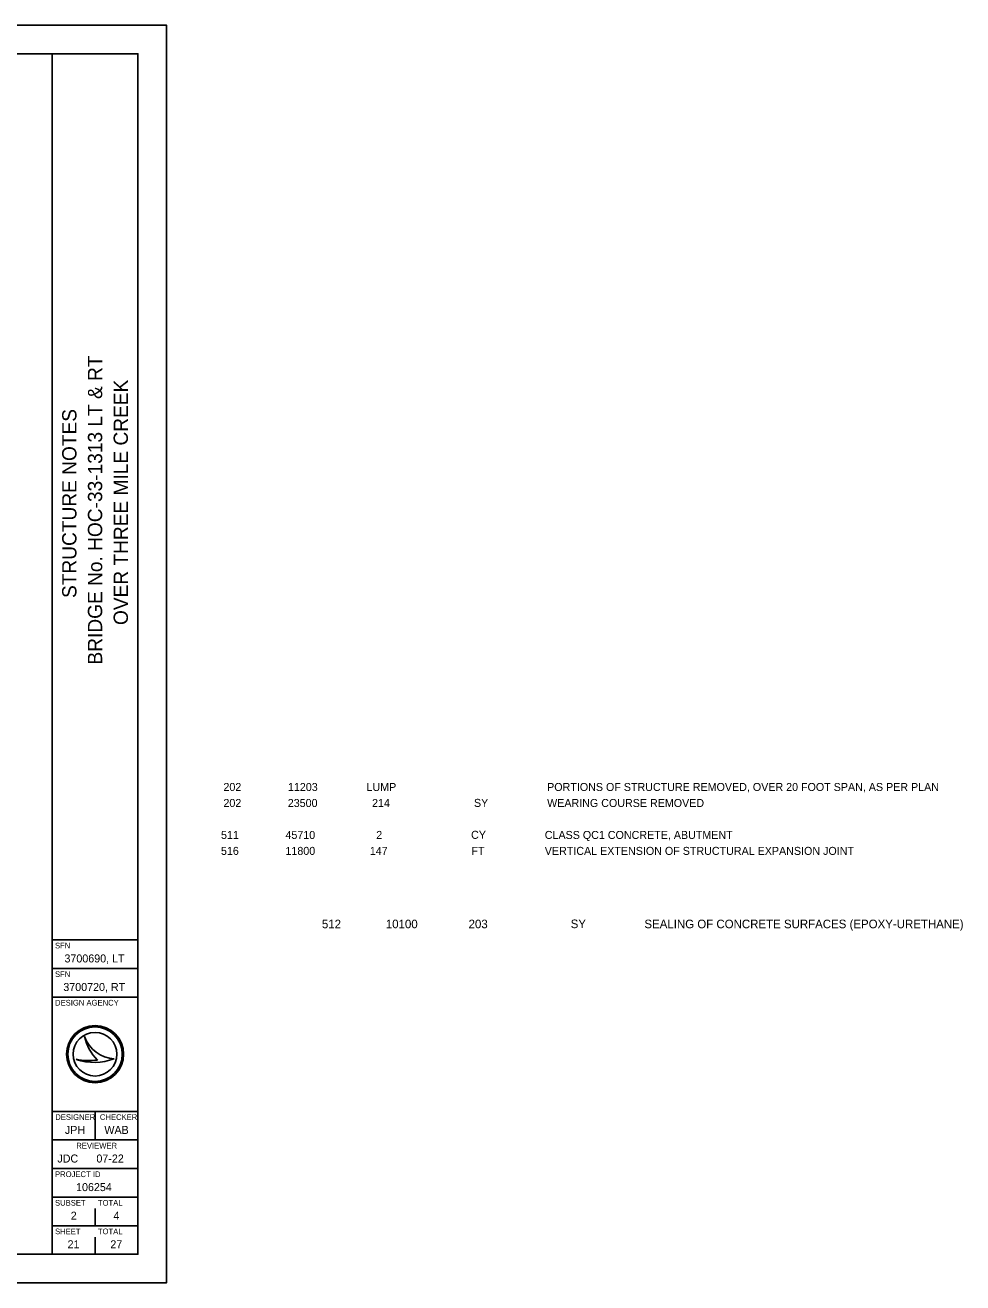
# Model space of a CAD drawing. Extents: x 55 to 102.9, y -8.3 to 13.7.
# Drawn here: x 86.49 to 102.89, y -8.33 to 13.67 of the extents above; entities that cross this region are included whole.
import ezdxf

# ---------------------------------------------------------------- set-up
doc = ezdxf.new("R2010")
doc.units = 0
for name, color, linetype in [('BR_P_Gen_Text', 7, 'Continuous'), ('SH_Border', 7, 'Continuous'), ('SH_Cut_Line', 7, 'Continuous'), ('SH_Data', 7, 'Continuous'), ('TX_P_1', 7, 'Continuous')]:
    doc.layers.add(name, color=color, linetype=linetype)

msp = doc.modelspace()

# ---------------------------------------------------------------- linework, layer by layer
at = {"layer": 'SH_Border'}
for p, q in [((86.958, -7.833), (86.958, 13.167)), ((86.958, -2.333), (88.458, -2.333)), ((86.958, -2.833), (88.458, -2.833)), ((86.958, -3.333), (88.458, -3.333)), ((86.958, -5.333), (88.458, -5.333)), ((87.708, -5.333), (87.708, -5.833)), ((86.958, -5.833), (88.458, -5.833)), ((86.958, -6.333), (88.458, -6.333)), ((86.958, -6.833), (88.458, -6.833)), ((86.958, -7.333), (88.458, -7.333))]:
    msp.add_line(p, q, dxfattribs=at)
msp.add_lwpolyline([(56.458, 13.167), (88.458, 13.167), (88.458, -7.833), (56.458, -7.833)], close=True, dxfattribs=at)
at = {"layer": 'SH_Cut_Line'}
msp.add_lwpolyline([(54.958, -8.333), (88.958, -8.333), (88.958, 13.667), (54.958, 13.667)], close=True, dxfattribs=at)
at = {"layer": 'SH_Data'}
for p, q in [((87.708, -2.658), (87.708, -2.658)), ((87.708, -3.158), (87.708, -3.158)), ((87.525, -4.023), (87.525, -4.023)), ((87.708, -4.333), (87.708, -4.333)), ((87.375, -4.423), (87.375, -4.423)), ((88.045, -4.414), (88.045, -4.414)), ((87.708, -7.333), (87.708, -7.033)), ((87.333, -7.658), (87.333, -7.658)), ((87.708, -7.833), (87.708, -7.533))]:
    msp.add_line(p, q, dxfattribs=at)
for radius in [0.5, 0.477, 0.477, 0.382]:
    msp.add_circle((87.708, -4.333), radius, dxfattribs=at)
for centre, radius, start, end in [((88.074, -3.835), 0.58, 198.9257, 198.9319), ((88.304, -3.863), 0.796, 191.6379, 191.6421), ((88.074, -3.835), 0.58, 198.9319, 267.1657), ((88.304, -3.863), 0.796, 191.6421, 226.0947), ((87.697, -3.463), 1.013, 251.4576, 290.0832), ((87.606, -3.178), 1.266, 259.4964, 259.4995), ((87.697, -3.463), 1.013, 251.4527, 251.4576), ((87.606, -3.178), 1.266, 259.4995, 276.6672)]:
    msp.add_arc(centre, radius, start, end, dxfattribs=at)

# ---------------------------------------------------------------- texts
at = {"layer": 'BR_P_Gen_Text'}
for s, height, p in [('202', 0.14, (89.954, 0.271)), ('11203', 0.14, (91.083, 0.271)), ('LUMP', 0.14, (92.457, 0.271)), ('202', 0.14, (89.954, -0.009)), ('23500', 0.14, (91.08, -0.009)), ('214', 0.14, (92.554, -0.009)), ('SY', 0.14, (94.337, -0.007)), ('511', 0.14, (89.912, -0.568)), ('45710', 0.14, (91.039, -0.568)), ('2', 0.14, (92.627, -0.568)), ('CY', 0.14, (94.287, -0.566)), ('516', 0.14, (89.911, -0.847)), ('11800', 0.14, (91.039, -0.847)), ('147', 0.14, (92.515, -0.847)), ('FT', 0.14, (94.294, -0.846)), ('512', 0.15, (91.677, -2.13)), ('10100', 0.15, (92.795, -2.13)), ('203', 0.15, (94.243, -2.13)), ('SY', 0.15, (96.029, -2.128))]:
    msp.add_text(s, height=height, dxfattribs=at).set_placement(p)
at = {"layer": 'SH_Data'}
for s, p in [('BRIDGE No. HOC-33-1313 LT & RT', (87.833, 2.483)), ('OVER THREE MILE CREEK', (88.283, 3.174)), ('STRUCTURE NOTES', (87.383, 3.647))]:
    msp.add_text(s, height=0.25, rotation=90, dxfattribs=at).set_placement(p)
for s, height, p in [('SFN', 0.1, (87.008, -2.483)), ('3700690, LT', 0.14, (87.173, -2.728)), ('SFN', 0.1, (87.008, -2.983)), ('3700720, RT', 0.14, (87.153, -3.228)), ('DESIGN AGENCY', 0.1, (87.008, -3.483)), ('DESIGNER', 0.1, (87.012, -5.483)), ('CHECKER', 0.1, (87.793, -5.483)), ('JPH', 0.14, (87.181, -5.728)), ('WAB', 0.14, (87.871, -5.728)), ('REVIEWER', 0.1, (87.38, -5.983)), ('JDC', 0.14, (87.049, -6.228)), ('07-22', 0.14, (87.732, -6.228)), ('PROJECT ID', 0.1, (87.008, -6.483)), ('106254', 0.14, (87.376, -6.728)), ('SUBSET', 0.1, (87.008, -6.983)), ('TOTAL', 0.1, (87.758, -6.983)), ('2', 0.14, (87.283, -7.228)), ('4', 0.14, (88.03, -7.228)), ('SHEET', 0.1, (87.008, -7.483)), ('TOTAL', 0.1, (87.758, -7.483)), ('21', 0.14, (87.227, -7.728)), ('27', 0.14, (87.976, -7.728))]:
    msp.add_text(s, height=height, dxfattribs=at).set_placement(p)
at = {"layer": 'TX_P_1'}
for s, height, p in [('PORTIONS OF STRUCTURE REMOVED, OVER 20 FOOT SPAN, AS PER PLAN', 0.14, (95.617, 0.271)), ('WEARING COURSE REMOVED', 0.14, (95.617, -0.009)), ('CLASS QC1 CONCRETE, ABUTMENT', 0.14, (95.576, -0.568)), ('VERTICAL EXTENSION OF STRUCTURAL EXPANSION JOINT', 0.14, (95.576, -0.847)), ('SEALING OF CONCRETE SURFACES (EPOXY-URETHANE)', 0.15, (97.319, -2.13))]:
    msp.add_text(s, height=height, dxfattribs=at).set_placement(p)

doc.saveas('drawing.dxf')
